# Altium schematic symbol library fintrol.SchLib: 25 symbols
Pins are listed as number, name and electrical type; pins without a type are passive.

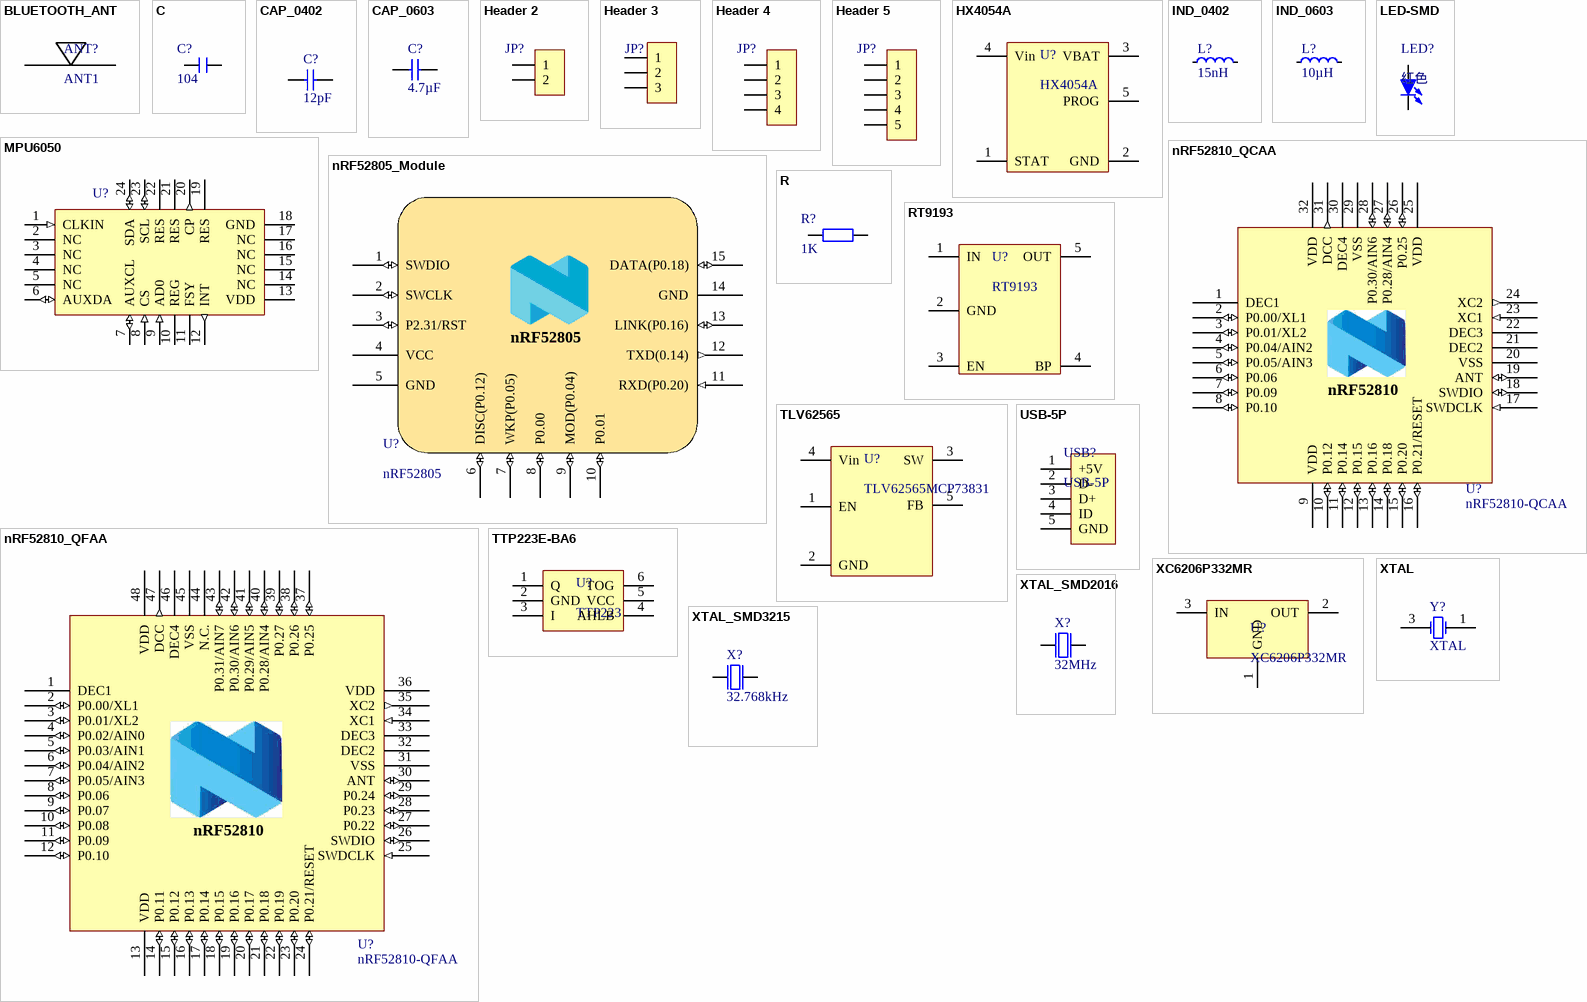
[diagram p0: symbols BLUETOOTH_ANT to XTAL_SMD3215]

## BLUETOOTH_ANT
designator ANT?, comment ANT1
PCB板载天线; 版权归属: 源创客
footprint BLUETOOTH_ANT (陶瓷表贴蓝牙天线)
pins: 1, 2

## C
designator C?, comment 104
无极性贴片电容; 版权归属: Fintrol
footprint C 0402_L (无极性贴片电容)
pins: 1, 2

## CAP_0402
designator C?, comment 12pF
Capacitor, NP0, ±2%; Part Number: C0402-12p; Note: 50V
footprint CAPC1005X04L
pins: 1, 2

## CAP_0603
designator C?, comment 4.7µF
Capacitor, X5R, ±10%; Part Number: C0603-4µ7; Note: 6.3V
footprint CAPC1608X06L
pins: 1, 2

## Header 2
designator JP?, comment HDR-1X2  (value not drawn)
2P接插件; 版权归属: 源创客
footprint MX 1.25-WI-2P (长：4.25mm，宽：1.8mm，高：3.3mm)
pins: 1, 2

## Header 3
designator JP?, comment HDR-1X3  (value not drawn)
3P接插件; 版权归属: 源创客
footprint MX 1.25-WI-3P (长：5.5mm，宽：1.8mm，高：3.3mm)
pins: 1, 2, 3

## Header 4
designator JP?, comment HDR-1X4  (value not drawn)
4P接插件; 版权归属: 源创客
footprint Debug-4P
footprint HDR2.54-LI-4P (排针，4脚)
pins: 1, 2, 3, 4

## Header 5
designator JP?, comment HDR-1X5  (value not drawn)
5P接插件; 版权归属: 源创客
footprint MX 1.25-WI-5P (长：8mm，宽：1.8mm，高：3.3mm)
pins: 1, 2, 3, 4, 5

## HX4054A
designator U?
Li-on Charging IC
footprint SOT23-5N (3x1.6x1.1mm(长宽高))
pins: 1 STAT, 2 GND, 3 VBAT, 4 Vin, 5 PROG

## IND_0402
designator L?, comment 15nH
High frequency chip inductor ±10%; Part Number: L0402-15n
footprint INDC1005X04L
pins: 1, 2

## IND_0603
designator L?, comment 10µH
Chip inductor, IDC,min = 50 mA, ±20%; Part Number: L0603-10µ
footprint INDC1608X06L
pins: 1, 2

## LED-SMD
designator LED?, comment 红色
贴片LED; 版权归属: 源创客
footprint LED2-0R6X1R0
pins: 1 A, 2 K

## MPU6050
designator U?  (value not drawn)
Three-axis MEMS IC
footprint MPU6050 (QFN, 24-Leads, Body 4.00x4.00mm, Pitch 0.50mm, Thermal Pad 2.70x2.60mm, IPC Medium Density)
pins: 1 CLKIN (in), 2 NC, 3 NC, 4 NC, 5 NC, 6 AUXDA (io), 7 AUXCL (io), 8 CS (in), 9 AD0 (in), 10 REG, 11 FSY, 12 INT (out), 13 VDD (power), 14 NC, 15 NC, 16 NC, 17 NC, 18 GND (power), 19 RES, 20 CP (out), 21 RES, 22 RES, 23 SCL (io), 24 SDA (io)

## nRF52805_Module
designator U?, comment nRF52805
Multi-protocol Bluetooth Low Energy, IEEE 802.15.4, ANT and 2.4GHz proprietary system-on-chip
footprint E104-BT5005A
pins: 1 SWDIO (io), 2 SWCLK (io), 3 P2.31/RST (io), 4 VCC (power), 5 GND (power), 6 DISC(P0.12) (io), 7 WKP(P0.05) (io), 8 P0.00 (io), 9 MOD(P0.04) (io), 10 P0.01 (io), 11 RXD(P0.20) (in), 12 TXD(0.14) (out), 13 LINK(P0.16) (io), 14 GND (power), 15 DATA(P0.18) (io)

## nRF52810_QCAA
designator U?, comment nRF52810-QCAA
Multi-protocol Bluetooth Low Energy, ANT and 2.4GHz proprietary system-on-chip; Manufacturer: Nordic Semiconductor; Note: nRF52810 - QFN32 5x5 0.5mm pitch
footprint Nordic_QFN50P500X500X90-33N (Footprint not found)
pins: 1 DEC1 (power), 2 P0.00/XL1 (io), 3 P0.01/XL2 (io), 4 P0.04/AIN2 (io), 5 P0.05/AIN3 (io), 6 P0.06 (io), 7 P0.09 (io), 8 P0.10 (io), 9 VDD (power), 10 P0.12 (io), 11 P0.14 (io), 12 P0.15 (io), 13 P0.16 (io), 14 P0.18 (io), 15 P0.20 (io), 16 P0.21/RESET (io), 17 SWDCLK (in), 18 SWDIO (io), 19 ANT (io), 20 VSS (power), 21 DEC2 (power), 22 DEC3 (power), 23 XC1 (in), 24 XC2 (out), 25 VDD (power), 26 P0.25 (io), 27 P0.28/AIN4 (io), 28 P0.30/AIN6 (io), 29 VSS (power), 30 DEC4 (power), 31 DCC (out), 32 VDD (power), 33 (power) hidden to GND

## nRF52810_QFAA
designator U?, comment nRF52810-QFAA
Multi-protocol Bluetooth Low Energy, ANT and 2.4GHz proprietary system-on-chip; Part Number: nRF52810-QFAABB; Manufacturer: Nordic Semiconductor; Note: nRF52810 - QFN48 6x6 0.4mm pitch
footprint QFN40P600X600X90-48N
pins: 1 DEC1 (power), 2 P0.00/XL1 (io), 3 P0.01/XL2 (io), 4 P0.02/AIN0 (io), 5 P0.03/AIN1 (io), 6 P0.04/AIN2 (io), 7 P0.05/AIN3 (io), 8 P0.06 (io), 9 P0.07 (io), 10 P0.08 (io), 11 P0.09 (io), 12 P0.10 (io), 13 VDD (power), 14 P0.11 (io), 15 P0.12 (io), 16 P0.13 (io), 17 P0.14 (io), 18 P0.15 (io), 19 P0.16 (io), 20 P0.17 (io), 21 P0.18 (io), 22 P0.19 (io), 23 P0.20 (io), 24 P0.21/RESET (io), 25 SWDCLK (in), 26 SWDIO (io), 27 P0.22 (io), 28 P0.23 (io), 29 P0.24 (io), 30 ANT (io), 31 VSS (power), 32 DEC2 (power), 33 DEC3 (power), 34 XC1 (in), 35 XC2 (out), 36 VDD (power), 37 P0.25 (io), 38 P0.26 (io), 39 P0.27 (io), 40 P0.28/AIN4 (io), 41 P0.29/AIN5 (io), 42 P0.30/AIN6 (io), 43 P0.31/AIN7 (io), 44 N.C. (power), 45 VSS (power), 46 DEC4 (power), 47 DCC (out), 48 VDD (power), 49 GND (power) hidden to GND

## R
designator R?, comment 1K
贴片电阻; 版权归属: 源创客
footprint R 0402_L (1/16W贴片电阻)
pins: 1, 2

## RT9193
designator U?
DC-DC Linear IC
footprint SOT23-5N (3x1.6x1.1mm(长宽高))
pins: 1 IN, 2 GND, 3 EN, 4 BP, 5 OUT

## TLV62565
designator U?, comment TLV62565MCP73831
DC-DC Down Convertor
footprint SOT23-5N (3x1.6x1.1mm(长宽高))
pins: 1 EN, 2 GND, 3 SW, 4 Vin, 5 FB

## TTP223E-BA6
designator U?, comment TTP223
Touching switch IC
footprint SOT23-6L (3x1.6x1.1mm(长宽高))
pins: 1 Q, 2 GND, 3 I, 4 AHLB, 5 VCC, 6 TOG

## USB-5P
designator USB?
微型USB母座; 版权归属: 源创客
footprint USB-micro_C (micro型USB ，5.7*7.8*2.5mm)
pins: 1 +5V, 2 D-, 3 D+, 4 ID, 5 GND

## XC6206P332MR
designator U?
DC-DC Linear IC / Cheap
footprint SOT23-3L (3x1.3x1mm(长宽高))
pins: 1 GND, 2 OUT, 3 IN

## XTAL
designator Y?
Crystal Oscillator
footprint R38 (Crystal, Thru-Hole; 2 Leads; Body 3.1 x 8.2 mm (Dia.xH))
simulation model XTAL (Spice Subcircuit)
pins: 1, 2 hidden to GND, 3, 4 hidden to GND

## XTAL_SMD2016
designator X?, comment 32MHz
XTAL SMD 2016, 32MHz, Cl=8pF, Total Tol: ±40ppm; Part Number: XTAL_SMD2016_32MHz_8pF_General
footprint BT-XTAL_2016
pins: 1 inp, 2 GND hidden to GND, 3 out, 4 GND hidden to GND

## XTAL_SMD3215
designator X?, comment 32.768kHz
XTAL SMD 3215, 32.768kHz, Cl=9pF, Total Tol: ±50ppm; Part Number: XTAL_SMD3215_32.768kHz_9pF_General
footprint XTAL_3215
pins: 1 inp, 2 out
